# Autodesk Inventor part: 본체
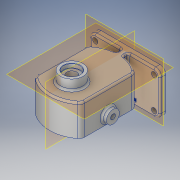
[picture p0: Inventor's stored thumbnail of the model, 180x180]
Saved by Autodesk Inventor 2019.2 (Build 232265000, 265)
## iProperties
Created: 2019-03
Part Number: 본체
Material: 알루미늄 6061
Document SubType Name: Modeling
Designer: User
Density: 2.7 g/cm^3
Appearance: 알루미늄 - 평지
Mass: 1187.2 g
Surface Area: 719.418 cm^2
Volume: 439.702 cm^3
Author: User
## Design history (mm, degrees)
sketch "스케치1"
  geometry: L1 (-84, 0)-(84, 0) reference; L2 (0, 14.6)-(0, -87.6) reference; L3 (-60, -73)-(60, -73); L4 (60, -73)-(60, 0); L5 (60, 0)-(-60, 0); L6 (-60, 0)-(-60, -73); L7 (-60, -73)-(60, 0); L8 (60, -73)-(-60, 0); 2 further points
  constraints: 12 end point, 3 midpoint, 2 parallel, 1 horizontal, 1 perpendicular, 1 point on line
  dimensions: "d0" = 73 distance of L3.end L4.end; "d1" = 120 distance of L3.start L3.end
extrude "돌출1" new body sketch "스케치1" distance "d2" = 10; taper "d3" = 0 deg
sketch "스케치3"
  geometry: L1 (0, 0)-(-43, 0); L2 (-43, 0)-(-43, 90.686); L3 (-43, 90.686)-(0, 90.686); L4 (0, 90.686)-(0, 0)
  constraints: 8 end point, 2 parallel, 1 horizontal, 1 perpendicular
  dimensions: "d6" = 43 distance of L1.start L1.end; "d7" = 90.68632 distance between parallel lines of L1 L3
extrude "돌출2" join sketch "스케치3" stored distance "d8" = 12; taper "d9" = 0 deg
sketch "스케치4"
  geometry: L1 (-40, 112.721)-(-40, 23.279); L2 (40, 112.721)-(40, 23.279); L3 (-200.879, 0)-(139.916, 0) reference; L4 (0, -37.6)-(0, 155.6) reference; L5 (91.231, 128)-(-24.785, 128); L6 (40, 112.721)-(-40, 112.721); L7 (40, 23.279)-(-40, 23.279); L8 (-60, -10)-(60, -10) reference; A1 r 60 centre (0, 68) between (40, 112.721) and (-40, 112.721); A2 r 60 centre (0, 68) between (-40, 23.279) and (40, 23.279); 1 further point
  constraints: 10 end point, 4 point on circle, 2 centre point, 2 horizontal, 2 perpendicular, 1 parallel, 1 point on line, 1 tangent, 1 other
  dimensions: "d23" = 80 distance between parallel lines of L2 L1; "d25" = 60 radius of A1; "d26" = 60 radius of A2; "d29" = 138 distance between parallel lines of L8 L5
extrude "돌출3" join sketch "스케치4" distance "d14" = 53; taper "d15" = 0 deg
sketch "스케치5"
  geometry: L1 (24, 90)-(24, 46); L2 (-24, 90)-(-24, 46); L3 (0, 155.6)-(0, -37.6) reference; L4 (-78.912, 68)-(103.855, 68); L5 (60, -10)-(-60, -10) reference; A1 r 24 centre (0, 90) between (24, 90) and (-24, 90); A2 r 24 centre (0, 46) between (-24, 46) and (24, 46); 1 further point
  constraints: 6 end point, 4 point on circle, 4 tangent, 2 centre point, 2 point on line, 1 horizontal, 1 parallel
  dimensions: "d21" = 44 distance of A2.centre A1.centre; "d22" = 24 radius of A1; "d27" = 22 distance from line of L1.end L4; "d28" = 78 distance between parallel lines of L5 L4
extrude "돌출4" cut sketch "스케치5" distance "d30" = 29; taper "d31" = 0 deg
sketch "스케치6"
  geometry: A1 r 24 centre (0, 90) between (24, 90) and (-24, 90) reference; 2 further points
  constraints: 1 coincident
hole "구멍1" sketch "스케치6" at (0, 90) diameter "d32" = 25; stored, may be unused: countersink angle "d36" = 82 deg, drill point angle "d38" = 0 deg; dims "d33" = 12, "d34" = 3.023, "d35" = 2, "d37" = 15
sketch "스케치7"
  geometry: A1 r 24 centre (0, 46) between (-24, 46) and (24, 46) reference; 2 further points
  constraints: 1 coincident
hole "구멍2" sketch "스케치7" at (0, 46) diameter "d39" = 25; stored, may be unused: countersink angle "d43" = 82 deg, drill point angle "d45" = 0 deg; dims "d40" = 12, "d41" = 3.023, "d42" = 2, "d44" = 15
sketch "스케치9"
  geometry: C1 r 19 at (60, -100); C2 r 12.5 at (60, -100) reference; 1 further point
  constraints: 1 centre point, 1 concentric
  dimensions: "d47" = 38 diameter of C1
extrude "돌출5" join sketch "스케치9" distance "d48" = 17; taper "d49" = 0 deg
sketch "스케치10"
  geometry: C1 r 19 at (0, 0) reference; 2 further points
  constraints: 1 coincident
hole "구멍3" sketch "스케치10" at (0, 0) diameter "d50" = 17; stored, may be unused: countersink angle "d54" = 82 deg, drill point angle "d56" = 0 deg; dims "d51" = 12, "d52" = 28, "d53" = 7.3, "d55" = 15
sketch "스케치11"
  geometry: L1 (-24, 46)-(-24, 90) reference; L2 (24, 90)-(24, 46) reference; L3 (0, 90)-(0, 121); A1 r 24 centre (0, 90) between (24, 90) and (-24, 90) reference; A2 r 24 centre (0, 46) between (-24, 46) and (24, 46) reference; 1 further point
  constraints: 2 end point, 1 vertical
  dimensions: "d57" = 31 distance of L3.start L3.end
hole "구멍4" sketch "스케치11" at (0, 121) diameter "d58" = 4.134; stored, may be unused: countersink angle "d62" = 82 deg, drill point angle "d64" = 118 deg; dims "d59" = 10, "d60" = 3.023, "d61" = 7.3, "d63" = 12
sketch "스케치12"
  geometry: L1 (24, 90)-(24, 46) reference; L2 (-24, 46)-(-24, 90) reference; L3 (0, 90)-(-31, 90); L4 (-31, 90)-(-31, 46); A1 r 24 centre (0, 90) between (24, 90) and (-24, 90) reference; A2 r 24 centre (0, 46) between (-24, 46) and (24, 46) reference; 1 further point
  constraints: 4 end point, 1 horizontal, 1 perpendicular
  dimensions: "d65" = 44 distance of L3.end L4.end; "d66" = 31 distance of L3.start L3.end
hole "구멍5" sketch "스케치12" at (-31, 90), (-31, 46) diameter "d67" = 4.134; stored, may be unused: countersink angle "d71" = 82 deg, drill point angle "d73" = 118 deg; dims "d68" = 10, "d69" = 3.023, "d70" = 7.3, "d72" = 12
sketch "스케치14"
  geometry: L1 (104.721, 0)-(104.721, -53) reference; L2 (44.721, 58.042)-(44.721, -160.194); L3 (-23.279, -73)-(-33.279, -73) reference; L4 (89.443, -53)-(0, -53) reference; C1 r 11 at (44.721, -39); 1 further point
  constraints: 2 end point, 1 centre point, 1 point on line, 1 vertical
  dimensions: "d77" = 22 diameter of C1; "d78" = 60 distance between parallel lines of L2 L1; "d117" = 14 distance from line of C1.centre L4
extrude "돌출6" join sketch "스케치14" distance "d80" = 8; taper "d81" = 0 deg
sketch "스케치15"
  geometry: C1 r 11 at (0, 0) reference; 2 further points
  constraints: 1 coincident
hole "구멍6" sketch "스케치15" at (0, 0) diameter "d82" = 8.376; stored, may be unused: countersink angle "d86" = 82 deg, drill point angle "d88" = 118 deg; dims "d83" = 40, "d84" = 3.023, "d85" = 7.3, "d87" = 27.3
fillet "모깎기1" dims "d89" = 10
fillet "모깎기2" dims "d90" = 3
fillet "모깎기3" dims "d91" = 3
fillet "모깎기4" dims "d92" = 3
fillet "모깎기5" dims "d93" = 10
fillet "모깎기6" dims "d94" = 3
fillet "모깎기7" dims "d95" = 3
fillet "모깎기8" dims "d96" = 0.5
chamfer "모따기2" distance "d100" = 1; stored, may be unused: second distance "d101" = 2, angle "d102" = 30 deg
sketch "스케치16"
  geometry: L1 (-50, -73)-(50, -73) reference; L2 (-60, -10)-(-60, -63) reference; 2 further points
  constraints: 1 other
  dimensions: "d103" = 10 distance from line of L1 point (0, -63); "d104" = 60 distance from line of point (0, -63) L2
feature "엠보싱1" sketch "스케치16" dims "d23" = 80, "d25" = 60, "d26" = 60, "d29" = 138, "d105" = 0.5, "d106" = 0
sketch "스케치17"
  geometry: C1 r 4.5 at (-50, -10); C2 r 4.5 at (-50, -63); A1 r 10 centre (-50, -10) between (-50, 0) and (-60, -10) reference; A2 r 10 centre (-50, -63) between (-60, -63) and (-50, -73) reference; 1 further point
  constraints: 2 centre point, 2 concentric
  dimensions: "d107" = 9 diameter of C1; "d108" = 9 diameter of C2
extrude "돌출7" cut sketch "스케치17" distance "d109" = 10; taper "d110" = 0 deg
chamfer "모따기3" distance "d111" = 1; stored, may be unused: second distance "d112" = 2, angle "d113" = 45 deg
chamfer "모따기4" distance "d114" = 0.7; stored, may be unused: second distance "d115" = 2, angle "d116" = 30 deg
node "솔리드1"
mirror "미러1"
pattern_linear "직사각형 패턴1" dims "d76" = 106
mirror "미러2"
mirror "미러3"
other parameters: "d24" = 83.65028
